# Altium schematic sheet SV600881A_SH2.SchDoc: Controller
size 431 x 279 mm; Date: Not shown in title block; ApprovedBy: Not shown in title block; CheckedBy: Not shown in title block; Author: Not shown in title block; CompanyName: Not shown in title block; DrawnBy: KNielson; Engineer: Eric Lee; Organization: Not shown in title block; Address1: Not shown in title block; Address2: Not shown in title block; Address3: Not shown in title block; Address4: Not shown in title block; DocumentNumber: 4; Revision: Use project parameter SCH_Rev; SheetNumber: 4; SheetTotal: 4; PageSetup: Record=PageOptions|CenterHorizontal=True|CenterVertical=True|PrintScale=0.96|XCorrection=1.00|YCorrection=1.00|PrintKind=0|BorderSize=5000000|LeftOffset=0|BottomOffset=0|Orientation=2|PaperLength=1000|PaperWidth=1000|Scale=100|PaperSource=7|PrintQuality=600|MediaType=1|DitherType=10|PaperKind=11" x 17"|PrintScaleMode=1
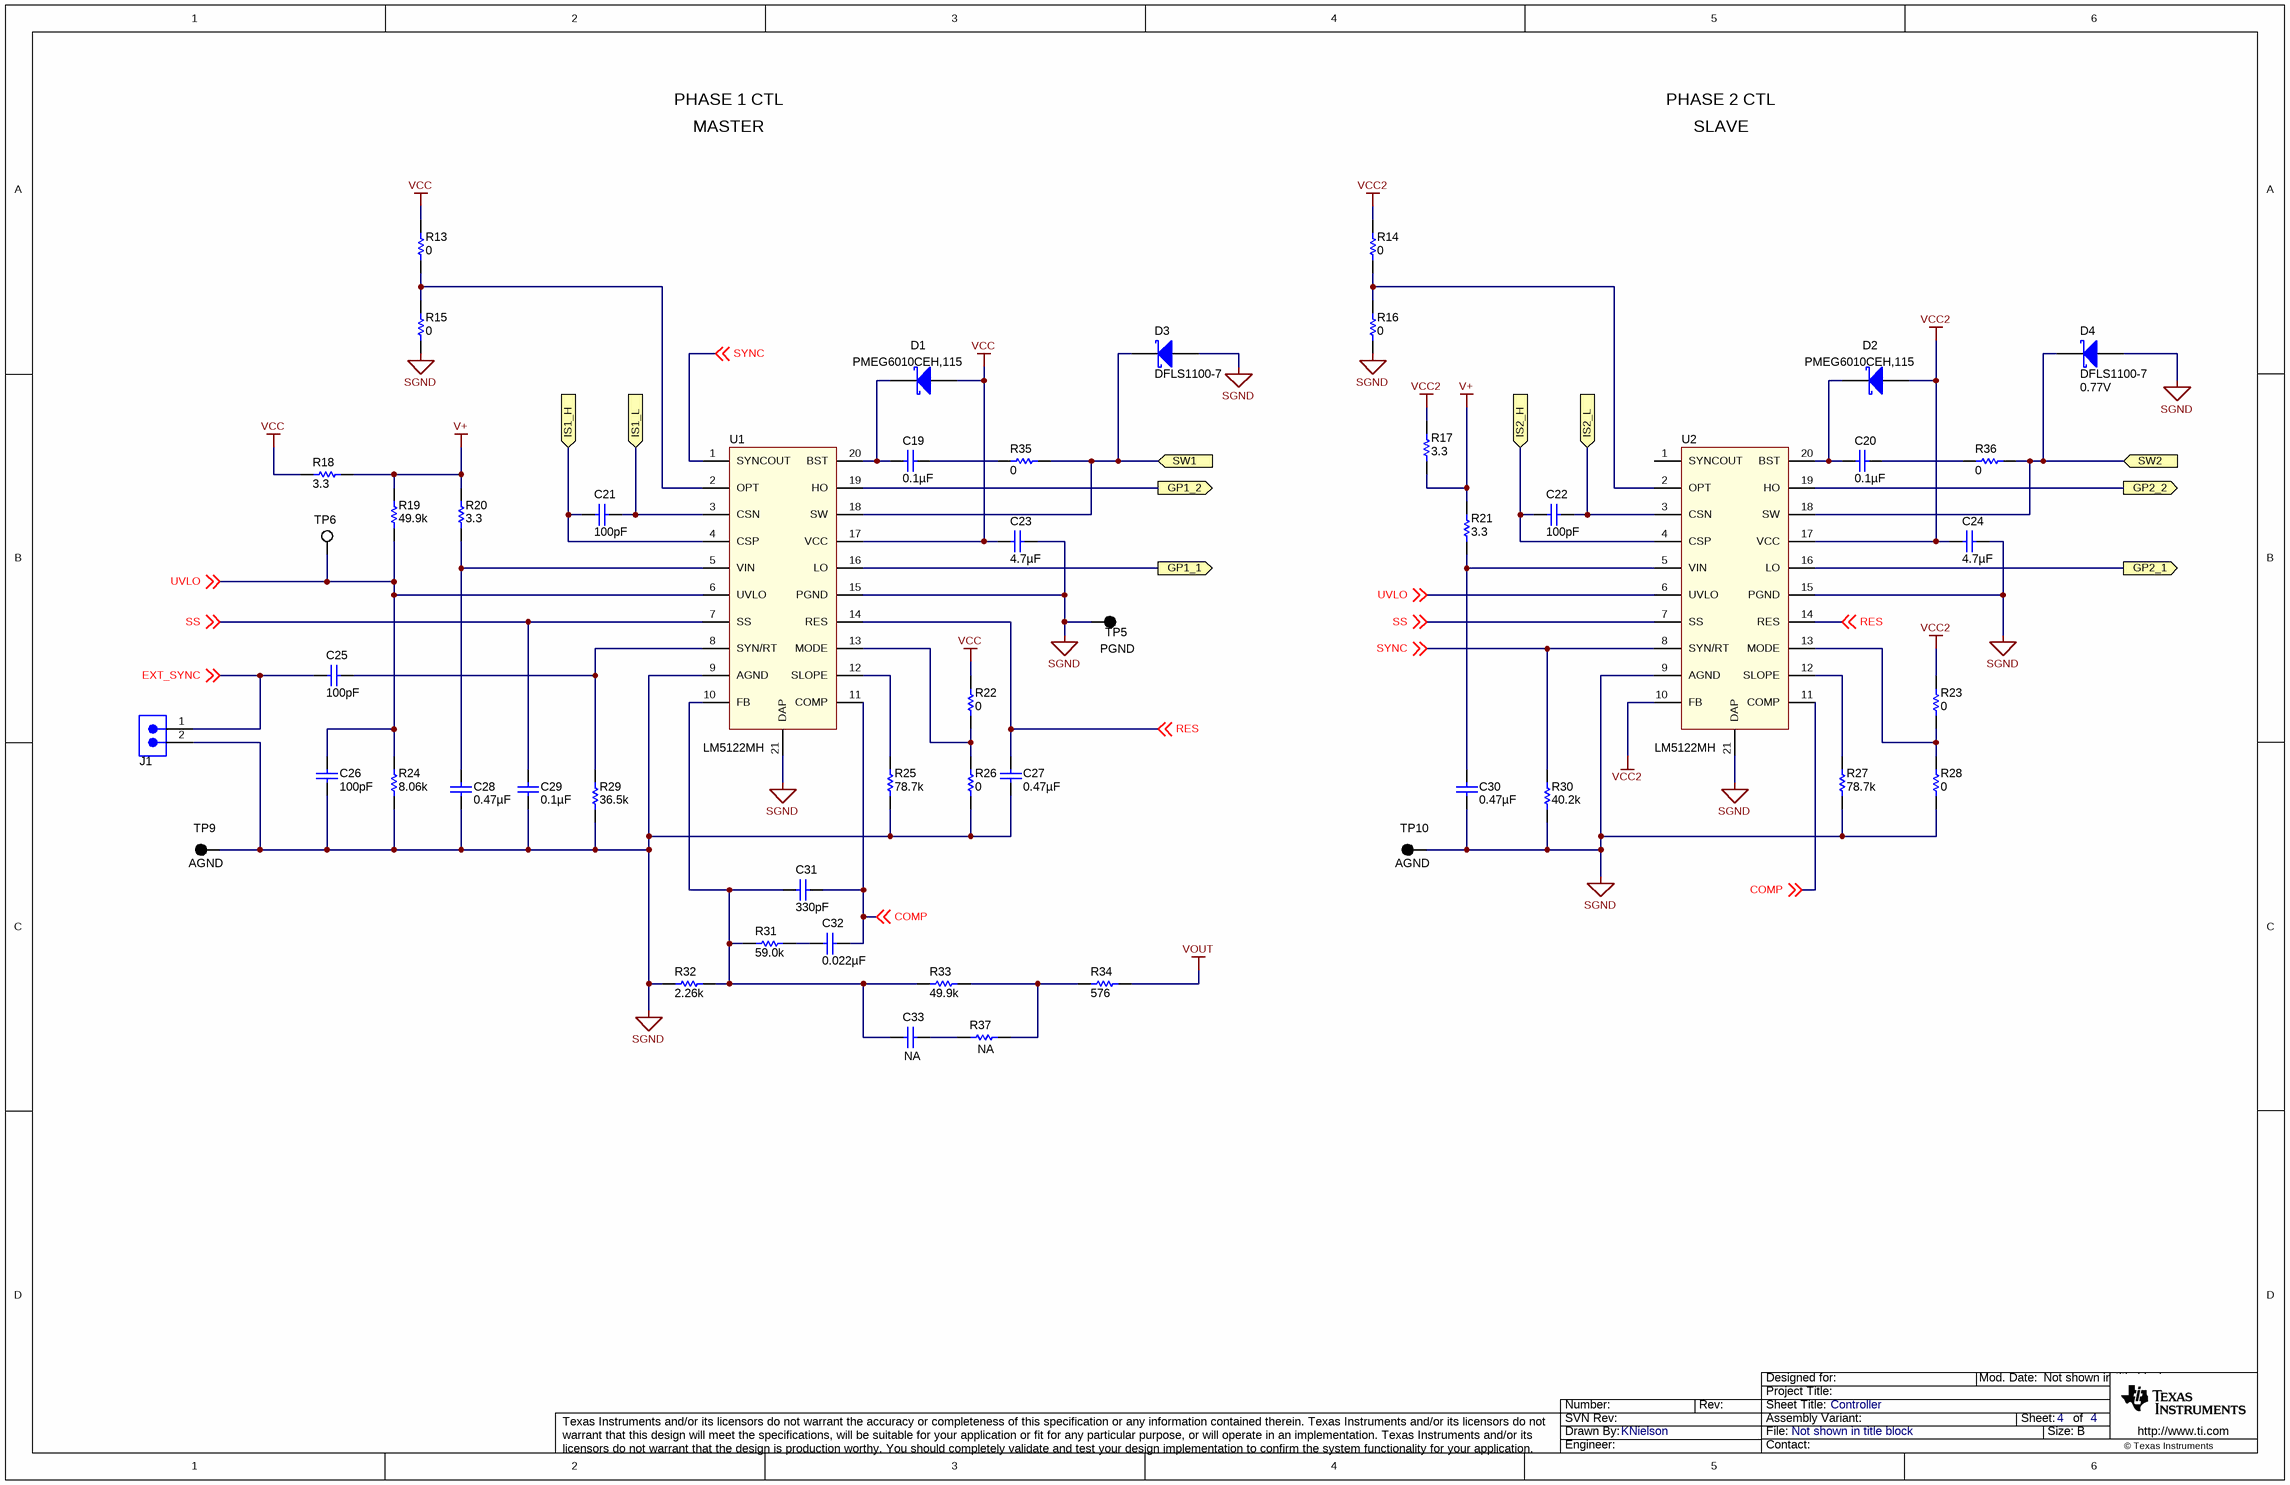
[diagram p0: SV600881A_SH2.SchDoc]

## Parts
C19  ValueDisplayed: 0.1µF  [0603_HV]  (hidden comment: GRM188R71E104KA01D)
C20  ValueDisplayed: 0.1µF  [0603_HV]  (hidden comment: GRM188R71E104KA01D)
C21  ValueDisplayed: 100pF  [0603_HV]  (hidden comment: GRM1885C1H101JA01D)
C22  ValueDisplayed: 100pF  [0603_HV]  (hidden comment: GRM1885C1H101JA01D)
C23  ValueDisplayed: 4.7µF  [0805_HV]  (hidden comment: GRM21BR71C475KA73L)
C24  ValueDisplayed: 4.7µF  [0805_HV]  (hidden comment: GRM21BR71C475KA73L)
C25  ValueDisplayed: 100pF  [0603_HV]  (hidden comment: GRM1885C1H101JA01D)
C26  ValueDisplayed: 100pF  [0603_HV]  (hidden comment: GRM1885C1H101JA01D)
C27  ValueDisplayed: 0.47µF  [0603_HV]  (hidden comment: GRM188R71E474KA12D)
C28  ValueDisplayed: 0.47µF  [0603_HV]  (hidden comment: GRM188R71E474KA12D)
C29  ValueDisplayed: 0.1µF  [0603_HV]  (hidden comment: GRM188R71E104KA01D)
C30  ValueDisplayed: 0.47µF  [0603_HV]  (hidden comment: GRM188R71E474KA12D)
C31  ValueDisplayed: 330pF  [0603_HV]  (hidden comment: C0603C331K5RACTU)
C32  ValueDisplayed: 0.022µF  [0603_HV]  (hidden comment: C0603C223K5RACTU)
C33  NA  [0603_HV]
D1  PMEG6010CEH,115  [SOD-123F]
D2  PMEG6010CEH,115  [SOD-123F]
D3  DFLS1100-7  [powerDI123]
D4  DFLS1100-7  value 0.77V  [powerDI123]
J1  TSW-102-07-G-S  [TSW-102-07-G-S]  (value not drawn)
R13  value 0  [0603_HV]  (hidden comment: ERJ-3GEY0R00V)
R14  value 0  [0603_HV]  (hidden comment: ERJ-3GEY0R00V)
R15  value 0  [0603_HV]  (hidden comment: ERJ-3GEY0R00V)
R16  value 0  [0603_HV]  (hidden comment: ERJ-3GEY0R00V)
R17  value 3.3  [0603_HV]  (hidden comment: CRCW06033R30JNEA)
R18  value 3.3  [0603_HV]  (hidden comment: CRCW06033R30JNEA)
R19  value 49.9k  [0603_HV]  (hidden comment: CRCW060349K9FKEA)
R20  value 3.3  [0603_HV]  (hidden comment: CRCW06033R30JNEA)
R21  value 3.3  [0603_HV]  (hidden comment: CRCW06033R30JNEA)
R22  value 0  [0603_HV]  (hidden comment: ERJ-3GEY0R00V)
R23  value 0  [0603_HV]  (hidden comment: ERJ-3GEY0R00V)
R24  value 8.06k  [0603_HV]  (hidden comment: CRCW06038K06FKEA)
R25  value 78.7k  [0603_HV]  (hidden comment: CRCW060378K7FKEA)
R26  value 0  [0603_HV]  (hidden comment: ERJ-3GEY0R00V)
R27  value 78.7k  [0603_HV]  (hidden comment: CRCW060378K7FKEA)
R28  value 0  [0603_HV]  (hidden comment: ERJ-3GEY0R00V)
R29  value 36.5k  [0603_HV]  (hidden comment: CRCW060336K5FKEA)
R30  value 40.2k  [0603_HV]  (hidden comment: CRCW060340K2FKEA)
R31  value 59.0k  [0603_HV]  (hidden comment: CRCW060359K0FKEA)
R32  value 2.26k  [0603_HV]  (hidden comment: CRCW06032K26FKEA)
R33  value 49.9k  [0603_HV]  (hidden comment: CRCW060349K9FKEA)
R34  value 576  [0805_HV]  (hidden comment: CRCW0805576RFKEA)
R35  value 0  [0603_HV]  (hidden comment: ERJ-3GEY0R00V)
R36  value 0  [0603_HV]  (hidden comment: ERJ-3GEY0R00V)
R37  NA  [0603_HV]
TP5  5011  [Keystone5011]  (value not drawn)
TP6  5002  [Keystone5002]  (value not drawn)
TP9  5001  [Keystone5001]  (value not drawn)
TP10  5001  [Keystone5001]  (value not drawn)
U1  LM5122MH  [MXA20A_L]
U2  LM5122MH  [MXA20A_L]

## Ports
GP1_1, GP1_2, GP2_1, GP2_2, IS1_H, IS1_L, IS2_H, IS2_L, SW1, SW2

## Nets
SGND: C23.1 C24.1 C26.2 C27.2 C28.2 C29.2 C30.2 D3.2(A) D4.2(A) J1.2 R15.1 R16.1 R24.1 R25.1 R26.1 R27.1 R28.1 R29.1 R30.1 R32.2 TP5.1 TP9.1 TP10.1 U1.9(AGND) U1.15(PGND) U1.21(DAP) U2.9(AGND) U2.15(PGND) U2.21(DAP)
V+: R17.2 R18.1 R19.2 R20.2 R21.2
VCC: C23.2 D1.2(A) R13.2 R18.2 R22.2 U1.17(VCC)
VCC2: C24.2 D2.2(A) R14.2 R17.1 R23.2 U2.10(FB) U2.17(VCC)
VOUT: R34.1
COMP: C31.2 C32.2 U1.11(COMP) U2.11(COMP) ; off-sheet COMP
EXT_SYNC: C25.2 J1.1 ; off-sheet EXT_SYNC
GP1_1: U1.16(LO) ; port GP1_1
GP1_2: U1.19(HO) ; port GP1_2
GP2_1: U2.16(LO) ; port GP2_1
GP2_2: U2.19(HO) ; port GP2_2
IS1_H: C21.2 U1.4(CSP) ; port IS1_H
IS1_L: C21.1 U1.3(CSN) ; port IS1_L
IS2_H: C22.2 U2.4(CSP) ; port IS2_H
IS2_L: C22.1 U2.3(CSN) ; port IS2_L
RES: C27.1 U1.14(RES) U2.14(RES) ; off-sheet RES
SS: C29.1 U1.7(SS) U2.7(SS) ; off-sheet SS
SW1: D3.1(K) R35.1 U1.18(SW) ; port SW1
SW2: D4.1(K) R36.1 U2.18(SW) ; port SW2
SYNC: R30.2 U1.1(SYNCOUT) U2.8(SYN/RT) ; off-sheet SYNC
UVLO: C26.1 R19.1 R24.2 TP6.1 U1.6(UVLO) U2.6(UVLO) ; off-sheet UVLO
NetC19_1: C19.1 R35.2
NetC19_2: C19.2 D1.1(K) U1.20(BST)
NetC20_1: C20.1 R36.2
NetC20_2: C20.2 D2.1(K) U2.20(BST)
NetC25_1: C25.1 R29.2 U1.8(SYN/RT)
NetC28_1: C28.1 R20.1 U1.5(VIN)
NetC30_1: C30.1 R21.1 U2.5(VIN)
NetC31_1: C31.1 C33.2 R31.1 R32.1 R33.1 U1.10(FB)
NetC32_1: C32.1 R31.2
NetC33_1: C33.1 R37.1
NetR13_1: R13.1 R15.2 U1.2(OPT)
NetR14_1: R14.1 R16.2 U2.2(OPT)
NetR22_1: R22.1 R26.2 U1.13(MODE)
NetR23_1: R23.1 R28.2 U2.13(MODE)
NetR25_2: R25.2 U1.12(SLOPE)
NetR27_2: R27.2 U2.12(SLOPE)
NetR33_2: R33.2 R34.2 R37.2

Not connected (* = marked no-connect by the designer): U2 1(SYNCOUT)

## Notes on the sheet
- PHASE 1 CTL
- PHASE 2 CTL
- MASTER
- SLAVE
- (near TP5) PGND
- (near TP9) AGND
- (near TP10) AGND

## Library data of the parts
C19 C20 C29 = GRM188R71E104KA01D: CAP, CERM, 0.1uF, 25V, +/-10%, X7R, 0603; Manufacturer: MuRata; Polarized: N; CompType: Capacitor; U/M: EA; Cap_F: 0.0000001; Tolerance_%: 10; VDC_V: 25; TaMin_C: -55; TaMax_C: 125; Cap_Case: 0603
C21 C22 C25 C26 = GRM1885C1H101JA01D: CAP, CERM, 100pF, 50V, +/-5%, C0G/NP0, 0603; Manufacturer: MuRata; Polarized: N; CompType: Capacitor; U/M: EA; Cap_F: 0.0000000001; Tolerance_%: 5; VDC_V: 50; TaMin_C: -55; TaMax_C: 125; Cap_Case: 0603
C23 C24 = GRM21BR71C475KA73L: CAP, CERM, 4.7uF, 16V, +/-10%, X7R, 0805; Manufacturer: MuRata; CompType: Capacitor; U/M: EA; Tolerance_%: 10; VDC_V: 16; Polarized: N; Cap_F: 0.0000047; ESR_Ohm: 0.006; Value1: 0.006 ohm; TaMin_C: -55; TaMax_C: 125; Cap_Case: 0805
C27 C28 C30 = GRM188R71E474KA12D: CAP, CERM, 0.47uF, 25V, +/-10%, X7R, 0603; Manufacturer: MuRata; Polarized: N; CompType: Capacitor; U/M: EA; Cap_F: 0.00000047; Tolerance_%: 10; VDC_V: 25; TaMin_C: -55; TaMax_C: 125; Cap_Case: 0603
C31 = C0603C331K5RACTU: CAP, CERM, 330pF, 50V, +/-10%, X7R, 0603; Manufacturer: Kemet; Polarized: N; CompType: Capacitor; U/M: EA; Cap_F: 0.00000000033; Tolerance_%: 10; VDC_V: 50; TaMin_C: -55; TaMax_C: 125; Cap_Case: 0603
C32 = C0603C223K5RACTU: CAP, CERM, 0.022uF, 50V, +/-10%, X7R, 0603; Manufacturer: Kemet; Polarized: N; CompType: Capacitor; U/M: EA; Cap_F: 0.000000022; Tolerance_%: 10; VDC_V: 50; TaMin_C: -55; TaMax_C: 125; Cap_Case: 0603
C33 = Capacitor: CAP, CERM, xxxF, xxV, [TempCo], xx%, [PackageReference]; Manufacturer: Used in BOM report; Polarized: N; U/M: EA
D1 D2 = PMEG6010CEH,115: Diode, Schottky, 60V, 1A, SOD-123F; Manufacturer: NXP Semiconductor; U/M: EA; Vf_V: 0.57; Io_A: 1; Vr_V: 60; TJmax_C: 150; Value: 0.57V
D3 = DFLS1100-7: Diode, Schottky, 100V, 1A, PowerDI123; Manufacturer: Diodes Inc.; Value: 0.77V; U/M: EA; Vf_V: 0.77; Io_A: 1; Vr_V: 100; TJmax_C: 175; RJC_CperW: 7
D4 = DFLS1100-7: Diode, Schottky, 100V, 1A, PowerDI123; Manufacturer: Diodes Inc.; U/M: EA; Vf_V: 0.77; Io_A: 1; Vr_V: 100; TJmax_C: 175; RJC_CperW: 7
J1 = TSW-102-07-G-S: Header, TH, 100mil, 2x1, Gold plated, 230 mil above insulator; Manufacturer: Samtec, Inc.; U/M: EA
R13-R16 R22 R23 R26 R28 R35 R36 = ERJ-3GEY0R00V: RES, 0 ohm, 5%, 0.1W, 0603; Manufacturer: Panasonic; CompType: Resistor; Value_Code: 0000; Tolerance_%: 5; Power_W: 0.1; VDC_V: 50; TempCo: 600 ppm/C; EIA_Code: E24; U/M: EA
R17 R18 R20 R21 = CRCW06033R30JNEA: RES, 3.3 ohm, 5%, 0.1W, 0603; Manufacturer: Vishay-Dale; CompType: Resistor; Value_Code: 3R30; Tolerance_%: 5; Power_W: 0.1; VDC_V: 75; TempCo: 200 ppm/C; EIA_Code: E24; U/M: EA
R19 R33 = CRCW060349K9FKEA: RES, 49.9k ohm, 1%, 0.1W, 0603; Manufacturer: Vishay-Dale; CompType: Resistor; Res_ohm: 49900; Value_Code: 49k9; Tolerance_%: 1; Power_W: 0.1; VDC_V: 75; TempCo: 100 ppm/C; EIA_Code: E96; U/M: EA
R24 = CRCW06038K06FKEA: RES, 8.06k ohm, 1%, 0.1W, 0603; Manufacturer: Vishay-Dale; Alternate PartNumber: Equivalent; Alternate Manufacturer: Any; CompType: Resistor; Res_ohm: 8060; Value_Code: 8k06; Tolerance_%: 1; Power_W: 0.1; VDC_V: 75; TempCo: 100 ppm/C; EIA_Code: E96; U/M: EA
R25 R27 = CRCW060378K7FKEA: RES, 78.7k ohm, 1%, 0.1W, 0603; Manufacturer: Vishay-Dale; Alternate PartNumber: Equivalent; Alternate Manufacturer: Any; CompType: Resistor; Res_ohm: 78700; Value_Code: 78k7; Tolerance_%: 1; Power_W: 0.1; VDC_V: 75; TempCo: 100 ppm/C; EIA_Code: E96; U/M: EA
R29 = CRCW060336K5FKEA: RES, 36.5k ohm, 1%, 0.1W, 0603; Manufacturer: Vishay-Dale; Alternate PartNumber: Equivalent; Alternate Manufacturer: Any; CompType: Resistor; Res_ohm: 36500; Value_Code: 36k5; Tolerance_%: 1; Power_W: 0.1; VDC_V: 75; TempCo: 100 ppm/C; EIA_Code: E96; U/M: EA
R30 = CRCW060340K2FKEA: RES, 40.2k ohm, 1%, 0.1W, 0603; Manufacturer: Vishay-Dale; CompType: Resistor; Res_ohm: 40200; Value_Code: 40k2; Tolerance_%: 1; Power_W: 0.1; VDC_V: 75; TempCo: 100 ppm/C; EIA_Code: E96; U/M: EA
R31 = CRCW060359K0FKEA: RES, 59.0k ohm, 1%, 0.1W, 0603; Manufacturer: Vishay-Dale; CompType: Resistor; Res_ohm: 59000; Value_Code: 59k0; Tolerance_%: 1; Power_W: 0.1; VDC_V: 75; TempCo: 100 ppm/C; EIA_Code: E96; U/M: EA
R32 = CRCW06032K26FKEA: RES, 2.26k ohm, 1%, 0.1W, 0603; Manufacturer: Vishay-Dale; CompType: Resistor; Res_ohm: 2260; Value_Code: 2k26; Tolerance_%: 1; Power_W: 0.1; VDC_V: 75; TempCo: 100 ppm/C; EIA_Code: E96; U/M: EA
R34 = CRCW0805576RFKEA: RES, 576 ohm, 1%, 0.125W, 0805; Manufacturer: Vishay-Dale; Alternate PartNumber: Equivalent; Alternate Manufacturer: Any; CompType: Resistor; Value_Code: 576R; Tolerance_%: 1; Power_W: 0.125; VDC_V: 150; TempCo: 100 ppm/C; EIA_Code: E96; U/M: EA
R37 = Resistor: RES, xxx ohm, x%, xW, [PackageReference]; Manufacturer: Used in BOM report; U/M: EA
TP5 = 5011: Test Point, TH, Multipurpose, Black; Manufacturer: Keystone; CompType: Test Point Loop; U/M: EA
TP6 = 5002: Test Point, TH, Miniature, White; Manufacturer: Keystone; CompType: Test Point Loop; U/M: EA
TP9 TP10 = 5001: Test Point, TH, Miniature, Black; Manufacturer: Keystone; CompType: Test Point Loop; U/M: EA
U1 U2 = LM5122: Manufacturer: TI; SymbolCreator: bkinsc; CompType: IC; U/M: EA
